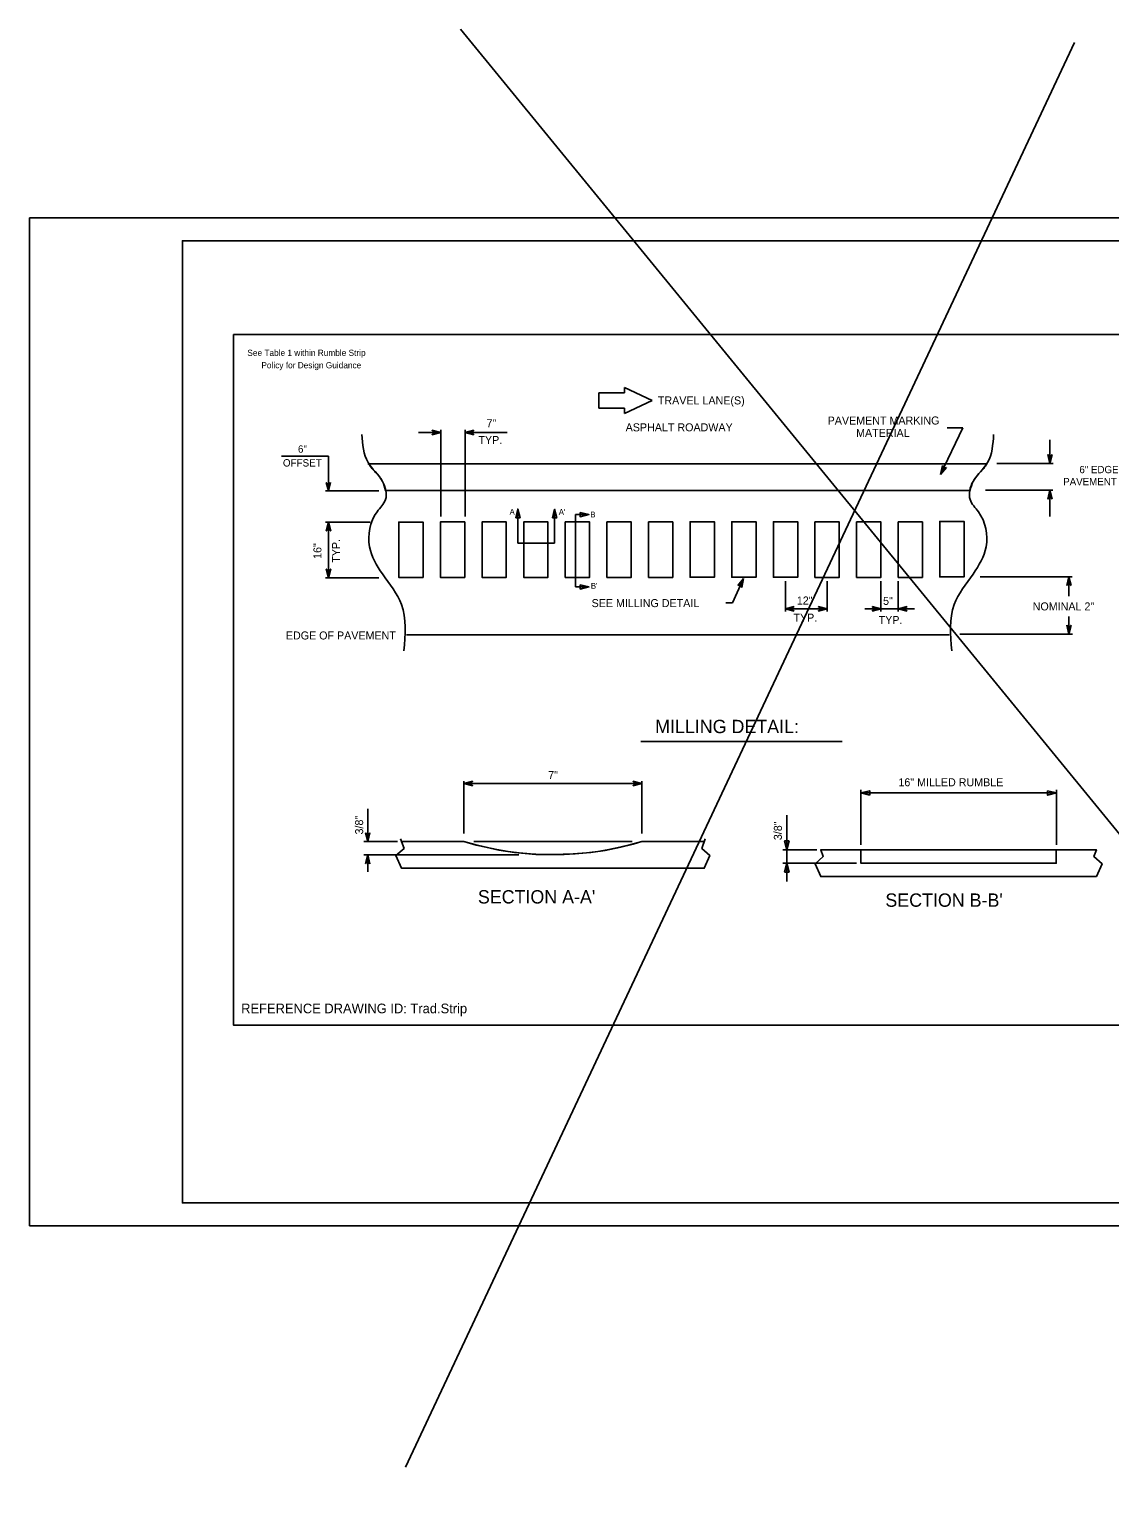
# Model space of a CAD drawing. Extents: x 1994737 to 2001433, y 527447 to 529360.
# Drawn here: x 1999305 to 2000714, y 527447 to 529360 of the extents above; entities that cross this region are included whole.
import ezdxf

# ---------------------------------------------------------------- set-up
doc = ezdxf.new("R2010")
doc.units = 0
for name, color, linetype in [('Default', 7, 'Continuous'), ('GSBWFILL', 7, 'Continuous'), ('Old_Level_33', 7, 'Continuous'), ('Prop Sign E Yield Sign Ahead CELL', 7, 'Continuous'), ('Prop Support Two', 7, 'Continuous')]:
    doc.layers.add(name, color=color, linetype=linetype)

# ---------------------------------------------------------------- blocks, each defined once
blk = doc.blocks.new('DTF')
at = {"layer": 'Default'}
for p, q in [((-19.936, 2.9115), (-19.9395, -2.8845)), ((-10.33625, 2.90475), (-19.936, 2.9115)), ((-10.34125, -4.8615), (0, 0)), ((-10.33475, 4.8755), (-10.33625, 2.90475)), ((0, 0), (-10.33475, 4.8755)), ((-19.9395, -2.8845), (-10.3405, -2.891)), ((-10.3405, -2.891), (-10.34125, -4.8615))]:
    blk.add_line(p, q, dxfattribs=at)
blk = doc.blocks.new('TERM2')
at = {"layer": 'Default'}
for p, q in [((-6.25, 1.563), (0, 0)), ((-4.687, 0), (-6.25, 1.563)), ((0, 0), (-6.25, -1.563)), ((-6.25, -1.563), (-4.687, 0))]:
    blk.add_line(p, q, dxfattribs=at)
blk = doc.blocks.new('TERM')
at = {"layer": 'Default'}
blk.add_lwpolyline([(-6.25, 1.563), (0, 0), (-6.25, -1.563)], close=True, dxfattribs=at)

msp = doc.modelspace()

# ---------------------------------------------------------------- linework, layer by layer
at = {"layer": 'Default'}
for p, q in [((1999867.3, 529360.1), (2001433.1, 527447.3)), ((1999795.6, 527484.7), (2000668, 529343)), ((1999841.6, 528724.6), (1999841.6, 528837.5)), ((1999873.3, 528724.5), (1999873.3, 528837.5)), ((2000522.6, 528840.3), (2000493.3, 528779.3)), ((2000501.8, 528840.3), (2000522.6, 528840.3)), ((1999841.6, 528834.2), (1999812.7, 528834.2)), ((1999873.3, 528834.2), (1999928.2, 528834.2)), ((2000636, 528824.8), (2000636, 528793.8)), ((1999633.8, 528803.5), (1999695, 528803.5)), ((1999695, 528758.1), (1999695, 528803.5)), ((1999746.7, 528793.5), (2000554.2, 528793.5)), ((2000553.9, 528793.5), (1999747.6, 528793.5)), ((2000566.9, 528793.8), (2000640.1, 528793.8)), ((1999761, 528758.1), (1999691.4, 528758.1)), ((1999769.2, 528758.5), (2000532.4, 528758.5)), ((1999769.6, 528758.5), (2000531.8, 528758.5)), ((2000551.9, 528758.9), (2000639.8, 528758.9)), ((2000636, 528758.8), (2000636, 528724.6)), ((1999942.1, 528689.9), (1999942.1, 528734.3)), ((1999990, 528689.9), (1999990, 528734.1)), ((2000017.4, 528727.1), (2000017.4, 528632.7)), ((2000017.5, 528727.1), (2000034, 528727.1)), ((1999749.6, 528717), (1999691.3, 528717)), ((1999695.2, 528717), (1999695.2, 528644.6)), ((1999942.1, 528689.9), (1999990, 528689.9)), ((1999761, 528644.6), (1999691.3, 528644.6)), ((2000017.4, 528632.7), (2000034.1, 528632.7)), ((2000236.2, 528643.9), (2000222, 528612.1)), ((2000291.1, 528640.4), (2000291.1, 528600.7)), ((2000345.4, 528640.4), (2000345.4, 528600.7)), ((2000415.4, 528640.4), (2000415.4, 528600.7)), ((2000438, 528640.4), (2000438, 528600.7)), ((2000545.2, 528646), (2000664.8, 528646)), ((2000660.7, 528620.9), (2000660.7, 528646)), ((2000222.1, 528612.1), (2000213.2, 528612.1)), ((2000290.9, 528604.1), (2000345.4, 528604.1)), ((2000394.6, 528604.1), (2000459.3, 528604.1)), ((2000660.7, 528571.2), (2000660.7, 528594)), ((1999796.8, 528570.4), (2000504.7, 528570.4)), ((2000518.5, 528571.2), (2000665.2, 528571.2)), ((2000102.7, 528431.2), (2000364.9, 528431.2)), ((1999871.9, 528311.1), (1999871.9, 528379.5)), ((2000103.8, 528311.1), (2000103.8, 528379.5)), ((1999871.9, 528376.3), (2000103.8, 528376.3)), ((2000389.5, 528296.3), (2000389.5, 528367.9)), ((2000389.5, 528364), (2000644.6, 528364)), ((2000644.6, 528296.3), (2000644.6, 528367.9)), ((1999746.3, 528300.5), (1999746.3, 528343.3)), ((2000292.9, 528289.8), (2000292.9, 528335.2)), ((1999789.2, 528304), (1999793.8, 528291.6)), ((2000186.4, 528304), (2000181.9, 528291.6)), ((1999785.4, 528300.5), (1999741.2, 528300.5)), ((1999943.5, 528283.1), (1999741.2, 528283.1)), ((1999746.3, 528283.1), (1999746.3, 528261.1)), ((1999793.8, 528291.6), (1999783.1, 528282.3)), ((1999790.5, 528300.5), (1999871.9, 528300.5)), ((1999884.7, 528300.5), (2000091, 528300.5)), ((2000103.8, 528300.5), (2000185.2, 528300.5)), ((2000181.9, 528291.6), (2000192.5, 528282.3)), ((2000332, 528289.8), (2000287.8, 528289.8)), ((2000292.9, 528272.4), (2000292.9, 528289.8)), ((2000337.1, 528289.8), (2000340.4, 528280.9)), ((2000337.1, 528289.8), (2000340.4, 528280.9)), ((2000389.5, 528289.8), (2000337.1, 528289.8)), ((2000337.1, 528289.8), (2000337.1, 528289.8)), ((2000337.1, 528289.8), (2000340.4, 528280.9)), ((2000340.4, 528280.9), (2000337.1, 528289.8)), ((2000337.1, 528289.8), (2000389.5, 528289.8)), ((2000389.5, 528289.8), (2000389.5, 528272.4)), ((2000389.5, 528272.4), (2000389.5, 528289.8)), ((2000389.5, 528289.8), (2000522.8, 528289.8)), ((2000522.8, 528289.8), (2000696.6, 528289.8)), ((2000644.3, 528289.8), (2000644.3, 528272.4)), ((2000644.3, 528289.8), (2000696.6, 528289.8)), ((2000644.3, 528288.1), (2000644.3, 528289.8)), ((2000644.3, 528272.4), (2000644.3, 528288.1)), ((2000696.6, 528289.8), (2000693.4, 528280.9)), ((2000696.6, 528289.8), (2000693.4, 528280.9)), ((1999783.1, 528282.3), (1999790.5, 528265.7)), ((1999790.5, 528265.7), (2000185.2, 528265.7)), ((2000192.5, 528282.3), (2000185.2, 528265.7)), ((2000383.7, 528272.4), (2000287.8, 528272.4)), ((2000292.9, 528272.4), (2000292.9, 528248.3)), ((2000340.4, 528280.9), (2000329.8, 528271.6)), ((2000340.4, 528280.9), (2000329.8, 528271.6)), ((2000329.8, 528271.6), (2000337.1, 528255)), ((2000329.8, 528271.6), (2000337.1, 528255)), ((2000389.5, 528272.4), (2000511.6, 528272.4)), ((2000511.6, 528272.4), (2000389.5, 528272.4)), ((2000511.6, 528272.4), (2000644.3, 528272.4)), ((2000511.6, 528272.4), (2000644.3, 528272.4)), ((2000693.4, 528280.9), (2000704, 528271.6)), ((2000693.4, 528280.9), (2000704, 528271.6)), ((2000704, 528271.6), (2000696.6, 528255)), ((2000704, 528271.6), (2000696.6, 528255)), ((2000337.1, 528255), (2000517.5, 528255)), ((2000337.1, 528255), (2000517.5, 528255)), ((2000517.5, 528255), (2000696.6, 528255)), ((2000696.6, 528255), (2000517.5, 528255))]:
    msp.add_line(p, q, dxfattribs=at)
for points in [[(1999571.4, 528962), (2000989.2, 528962), (2000989.2, 528061), (1999571.4, 528061)], [(1999939.3, 528722.9), (1999942.1, 528734.3), (1999945, 528722.9)], [(1999987.2, 528722.7), (1999990, 528734.1), (1999992.9, 528722.7)], [(2000023.3, 528729.9), (2000034.7, 528727.1), (2000023.3, 528724.2)], [(1999786.9, 528717.4), (1999818.5, 528717.4), (1999818.5, 528645.1), (1999786.9, 528645.1)], [(1999818.5, 528645.1), (1999786.9, 528645.1), (1999786.9, 528717.4), (1999818.5, 528717.4)], [(1999841.2, 528717.6), (1999872.9, 528717.6), (1999872.9, 528645.2), (1999841.2, 528645.2)], [(1999841.2, 528717.6), (1999872.9, 528717.6), (1999872.9, 528645.2), (1999841.2, 528645.2)], [(1999895.5, 528717.6), (1999927.1, 528717.6), (1999927.1, 528645.2), (1999895.5, 528645.2)], [(1999895.5, 528645.2), (1999927.1, 528645.2), (1999927.1, 528717.6), (1999895.5, 528717.6)], [(1999949.8, 528717.6), (1999981.4, 528717.6), (1999981.4, 528645.2), (1999949.8, 528645.2)], [(1999949.8, 528717.6), (1999981.4, 528717.6), (1999981.4, 528645.2), (1999949.8, 528645.2)], [(2000004, 528717.5), (2000035.6, 528717.5), (2000035.6, 528645.1), (2000004, 528645.1)], [(2000004, 528645.1), (2000035.6, 528645.1), (2000035.6, 528717.5), (2000004, 528717.5)], [(2000058.3, 528717.5), (2000089.9, 528717.5), (2000089.9, 528645.1), (2000058.3, 528645.1)], [(2000058.3, 528717.5), (2000089.9, 528717.5), (2000089.9, 528645.1), (2000058.3, 528645.1)], [(2000112.6, 528717.5), (2000144.2, 528717.5), (2000144.2, 528645.1), (2000112.6, 528645.1)], [(2000112.6, 528717.5), (2000144.2, 528717.5), (2000144.2, 528645.1), (2000112.6, 528645.1)], [(2000166.8, 528717.7), (2000198.5, 528717.7), (2000198.5, 528645.3), (2000166.8, 528645.3)], [(2000166.8, 528717.7), (2000198.5, 528717.7), (2000198.5, 528645.3), (2000166.8, 528645.3)], [(2000221.1, 528717.7), (2000252.8, 528717.7), (2000252.8, 528645.3), (2000221.1, 528645.3)], [(2000221.1, 528717.7), (2000252.8, 528717.7), (2000252.8, 528645.3), (2000221.1, 528645.3)], [(2000275.4, 528717.7), (2000307.1, 528717.7), (2000307.1, 528645.3), (2000275.4, 528645.3)], [(2000329.6, 528717.6), (2000361.3, 528717.6), (2000361.3, 528645.2), (2000329.6, 528645.2)], [(2000383.9, 528717.6), (2000415.5, 528717.6), (2000415.5, 528645.2), (2000383.9, 528645.2)], [(2000438.2, 528717.6), (2000469.8, 528717.6), (2000469.8, 528645.2), (2000438.2, 528645.2)], [(2000492.4, 528718.1), (2000524, 528718.1), (2000524, 528645.7), (2000492.4, 528645.7)], [(2000023.5, 528635.6), (2000034.9, 528632.7), (2000023.5, 528629.9)], [(2000103.8, 528300.5), (2000185.2, 528300.5), (2000181.9, 528291.6), (2000192.5, 528282.3), (2000185.2, 528265.7), (1999790.5, 528265.7), (1999783.1, 528282.3), (1999793.8, 528291.6), (1999790.5, 528300.5), (1999871.9, 528300.5), (1999887.6, 528296), (1999900.5, 528293.4), (1999917.3, 528289.5), (1999937.6, 528286.5), (1999965.6, 528283.9), (1999988.4, 528283.5), (2000014.3, 528284.4), (2000037.5, 528286.5), (2000056.1, 528289.1), (2000076.3, 528293.4), (2000092.3, 528297.3), (2000103.8, 528300.5)], [(2000644.3, 528289.8), (2000696.6, 528289.8), (2000693.4, 528280.9), (2000704, 528271.6), (2000696.6, 528255), (2000337.1, 528255), (2000329.8, 528271.6), (2000340.4, 528280.9), (2000337.1, 528289.8), (2000389.5, 528289.8), (2000389.5, 528272.4), (2000644.3, 528272.4)]]:
    msp.add_lwpolyline(points, close=True, dxfattribs=at)
for points in [[(1999786.9, 528645.1), (1999818.5, 528645.1), (1999818.5, 528717.4), (1999786.9, 528717.4), (1999786.9, 528645.1)], [(1999841.2, 528645.2), (1999872.9, 528645.2), (1999872.9, 528717.6), (1999841.2, 528717.6), (1999841.2, 528645.2)], [(1999895.5, 528645.2), (1999927.1, 528645.2), (1999927.1, 528717.6), (1999895.5, 528717.6), (1999895.5, 528645.2)], [(1999949.8, 528645.2), (1999981.4, 528645.2), (1999981.4, 528717.6), (1999949.8, 528717.6), (1999949.8, 528645.2)], [(2000004, 528645.1), (2000035.6, 528645.1), (2000035.6, 528717.5), (2000004, 528717.5), (2000004, 528645.1)], [(2000058.3, 528645.1), (2000089.9, 528645.1), (2000089.9, 528717.5), (2000058.3, 528717.5), (2000058.3, 528645.1)], [(2000112.6, 528645.1), (2000144.2, 528645.1), (2000144.2, 528717.5), (2000112.6, 528717.5), (2000112.6, 528645.1)], [(2000166.8, 528645.3), (2000198.5, 528645.3), (2000198.5, 528717.7), (2000166.8, 528717.7), (2000166.8, 528645.3)], [(2000221.1, 528645.3), (2000252.8, 528645.3), (2000252.8, 528717.7), (2000221.1, 528717.7), (2000221.1, 528645.3)], [(2000275.4, 528645.3), (2000307.1, 528645.3), (2000307.1, 528717.7), (2000275.4, 528717.7), (2000275.4, 528645.3)], [(2000329.6, 528645.2), (2000361.3, 528645.2), (2000361.3, 528717.6), (2000329.6, 528717.6), (2000329.6, 528645.2)], [(2000383.9, 528645.2), (2000415.5, 528645.2), (2000415.5, 528717.6), (2000383.9, 528717.6), (2000383.9, 528645.2)], [(2000438.2, 528645.2), (2000469.8, 528645.2), (2000469.8, 528717.6), (2000438.2, 528717.6), (2000438.2, 528645.2)], [(2000492.4, 528645.7), (2000524, 528645.7), (2000524, 528718.1), (2000492.4, 528718.1), (2000492.4, 528645.7)]]:
    msp.add_lwpolyline(points, dxfattribs=at)
msp.add_arc((1999987.8, 528689.6), 406, 253.4, 286.5999, dxfattribs=at)
for points in [[(1999738.8, 528831.7), (1999746.8, 528795.2), (1999765.6, 528770.4), (1999769.5, 528746.6), (1999758.6, 528730.8), (1999748.7, 528685.2), (1999765.6, 528649.6), (1999790.3, 528609.9), (1999793.5, 528549.4)], [(2000562.6, 528831.6), (2000554.7, 528795.1), (2000535.8, 528770.3), (2000531.9, 528746.6), (2000542.8, 528730.7), (2000552.7, 528685.1), (2000535.8, 528649.5), (2000511.1, 528609.9), (2000507.9, 528549.3)], [(1999747.6, 528793.5), (1999749.5, 528790.4), (1999751.8, 528787.4), (1999756.7, 528782), (1999761.6, 528776.5), (1999763.7, 528773.6), (1999765.6, 528770.4), (1999769.6, 528758.5)], [(2000531.8, 528758.5), (2000535.8, 528770.3), (2000537.7, 528773.5), (2000539.9, 528776.4), (2000544.7, 528781.9), (2000549.7, 528787.4), (2000551.9, 528790.4), (2000553.9, 528793.5)]]:
    msp.add_spline(points, degree=3, dxfattribs=at)
at = {"layer": 'GSBWFILL'}
for p, q in [((2001317.7, 529114.1), (1999305.1, 529114.1)), ((1999305.1, 529114.1), (1999305.1, 527799.4)), ((1999305.1, 527799.4), (2001317.7, 527799.4))]:
    msp.add_line(p, q, dxfattribs=at)
at = {"layer": 'Old_Level_33'}
msp.add_line((1999505.9, 529084.2), (1999505.9, 529084.2), dxfattribs=at)
at = {"layer": 'Prop Sign E Yield Sign Ahead CELL'}
msp.add_lwpolyline([(2001297.3, 529084.2), (1999504.7, 529084.2), (1999504.7, 527829.3), (2001297.3, 527829.3)], close=True, dxfattribs=at)
at = {"layer": 'Prop Support Two'}
msp.add_line((1999305.1, 527799.4), (1999305.1, 527799.4), dxfattribs=at)

# ---------------------------------------------------------------- block references
at = {"layer": 'Default', "xscale": 3.4793784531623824, "yscale": 3.4793784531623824}
msp.add_blockref('DTF', (2000117.2, 528875.8), dxfattribs=at)
at = {"layer": 'Default'}
for name, p, xscale, yscale, rotation in [('TERM2', (1999841.6, 528834.2), 1.8556685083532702, 1.8556685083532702, 2.7372046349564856e-11), ('TERM2', (1999873.3, 528834.2), 1.8556685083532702, 1.8556685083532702, -179.99999999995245), ('TERM2', (2000636, 528793.8), 1.8556685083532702, 1.8556685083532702, -89.99999999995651), ('TERM2', (2000493.3, 528779.3), 1.8556685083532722, 1.8556685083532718, -115.63251036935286), ('TERM2', (1999695, 528758.1), 1.7040114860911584, 1.7040114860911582, -89.99999999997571), ('TERM2', (2000636, 528758.8), 1.8556685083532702, 1.8556685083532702, 90.00000000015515), ('TERM2', (1999695.2, 528717), 1.8556685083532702, 1.8556685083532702, 89.99999999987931), ('TERM2', (1999695.2, 528644.6), 1.8556685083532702, 1.8556685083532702, -90.0000000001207), ('TERM2', (2000236.2, 528643.9), 1.8556685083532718, 1.8556685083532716, 65.81937702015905), ('TERM2', (2000660.7, 528646), 1.8556685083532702, 1.8556685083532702, 90.00000000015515), ('TERM2', (2000290.9, 528604.1), 1.8556685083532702, 1.8556685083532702, 179.99999999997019), ('TERM2', (2000345.4, 528604.1), 1.8556685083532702, 1.8556685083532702, -2.9817700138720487e-11), ('TERM2', (2000415.6, 528604.1), 1.8556685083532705, 1.8556685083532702, -0.009516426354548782), ('TERM2', (2000438.2, 528604.1), 1.855668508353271, 1.8556685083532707, -179.75274341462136), ('TERM2', (2000660.7, 528571.2), 1.8556685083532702, 1.8556685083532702, -89.99999999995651), ('TERM2', (1999871.9, 528376.3), 1.8556685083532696, 1.85566850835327, 179.99984077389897), ('TERM2', (2000103.8, 528376.3), 1.8556685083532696, 1.85566850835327, -0.0001592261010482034), ('TERM', (2000389.5, 528364), 1.8556685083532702, 1.8556685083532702, 179.9999999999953), ('TERM', (2000644.6, 528364), 1.8556685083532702, 1.8556685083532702, -4.686499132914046e-12), ('TERM2', (1999746.3, 528300.5), 1.855668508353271, 1.8556685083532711, -89.99968490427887), ('TERM2', (1999746.3, 528283.1), 1.8556685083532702, 1.8556685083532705, 89.99993359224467), ('TERM', (2000292.9, 528289.8), 1.8556685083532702, 1.8556685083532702, -90.0000000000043), ('TERM', (2000292.9, 528272.4), 1.8556685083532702, 1.8556685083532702, 89.99999999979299)]:
    msp.add_blockref(name, p, dxfattribs=dict(at, xscale=xscale, yscale=yscale, rotation=rotation))

# ---------------------------------------------------------------- texts
for s, height, rotation, p in [('See Table 1 within Rumble Strip', 8.074, 360, (1999589.4, 528934.1)), ('Policy for Design Guidance', 8.074, 360, (1999607.7, 528917.9)), ('TRAVEL LANE(S)', 10.438, 360, (2000124.7, 528870.8)), ('7"', 10.44, 360, (1999901.2, 528841)), ('ASPHALT ROADWAY', 10.438, 360, (2000082.7, 528835.7)), ('PAVEMENT MARKING', 10.438, 360, (2000346.1, 528844.6)), ('MATERIAL', 10.44, 360, (2000383.2, 528828.4)), ('TYP.', 10.44, 360, (1999890.7, 528819.2)), ('OFFSET', 9.59, 360, (1999635.8, 528789.8)), ('6"', 9.59, 360, (1999655.4, 528807.8)), ('6" EDGELINE', 9.489, 360, (2000674.4, 528781.1)), ('PAVEMENT MARKING', 9.489, 360, (2000653.3, 528765.3)), ('A', 7.61, 0, (1999931.3, 528726.9)), ("A'", 7.61, 0, (1999995.5, 528726.7)), ('B', 7.61, 0, (2000036.6, 528723.4)), ('16"', 10.44, 90, (1999686, 528669.3)), ('TYP.', 10.44, 90, (1999710.2, 528664.3)), ("B'", 7.61, 0, (2000037.3, 528630.4)), ('SEE MILLING DETAIL', 10.438, 360, (2000038.3, 528606.4)), ('12"', 10.44, 360, (2000305.9, 528609.8)), ('5"', 10.44, 360, (2000418.4, 528609.3)), ('NOMINAL 2"', 10.44, 360, (2000613.5, 528602.1)), ('TYP.', 10.44, 360, (2000301.5, 528587.4)), ('TYP.', 10.44, 360, (2000412.6, 528584.4)), ('EDGE OF PAVEMENT', 10.438, 360, (1999639.6, 528564.2)), ('MILLING DETAIL:', 17.397, 0, (2000121.2, 528442)), ('7"', 10.44, 0, (1999981.7, 528382.2)), ('16" MILLED RUMBLE', 10.438, 0, (2000438.4, 528372.7)), ('3/8"', 10.44, 90.0002, (1999740.4, 528309.8)), ('3/8"', 10.44, 90.0002, (2000286.4, 528302.4)), ("SECTION A-A'", 17.397, 0, (1999890, 528219.8)), ("SECTION B-B'", 17.397, 0, (2000421.4, 528215.5)), ('REFERENCE DRAWING ID: Trad.Strip', 12.592, 0, (1999581.3, 528076.6))]:
    msp.add_text(s, height=height, rotation=rotation, dxfattribs=at).set_placement(p)

doc.saveas('drawing.dxf')
